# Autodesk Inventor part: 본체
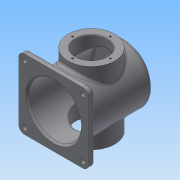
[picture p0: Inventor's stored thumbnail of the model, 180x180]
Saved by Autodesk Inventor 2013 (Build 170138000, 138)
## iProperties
Created: 2015-10
Part Number: 본체
Material: 일반
Document SubType Name: Modeling
Designer: Administrator
Density: 1 g/cm^3
Author: Administrator
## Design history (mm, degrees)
sketch "스케치1"
  geometry: C1 r 50 at (0, 0); 1 further point
  constraints: 1 centre point, 1 coincident
  dimensions: "d0" = 100 diameter of C1
extrude "돌출1" new body sketch "스케치1" stored distance "d1" = 110; taper "d2" = 0 deg
sketch "스케치2"
  geometry: C1 r 50 at (0, 0) reference; C2 r 40 at (0, 0)
  constraints: 1 centre point, 1 coincident
  dimensions: "d3" = 80 diameter of C2
extrude "돌출2" join sketch "스케치2" distance "d4" = 5; taper "d5" = 0 deg
sketch "스케치3"
  geometry: L1 (-60, 60)-(60, 60); L2 (60, 60)-(60, -60); L3 (60, -60)-(-60, -60); L4 (-60, -60)-(-60, 60); L5 (-60, 60)-(60, -60); L6 (60, 60)-(-60, -60); C1 r 50 at (0, 0) reference
  constraints: 12 end point, 2 midpoint, 2 parallel, 1 horizontal, 1 perpendicular
  dimensions: "d6" = 120 distance of L2.end L3.end; "d7" = 120 distance of L1.end L2.end
extrude "돌출3" join sketch "스케치3" distance "d8" = 10; taper "d9" = 0 deg
sketch "스케치4"
  geometry: C1 r 45 at (0, 0); 1 further point
  constraints: 1 centre point, 1 coincident
  dimensions: "d10" = 90 diameter of C1
extrude "돌출4" cut sketch "스케치4" distance "d11" = 112; taper "d12" = 0 deg
node "작업 평면1"
sketch "스케치6"
  geometry: C1 r 40 at (0, 0); 1 further point
  constraints: 1 centre point, 1 coincident
  dimensions: "d14" = 80 diameter of C1
extrude "돌출5" join sketch "스케치6" stored distance "d15" = 112; taper "d16" = 0 deg
sketch "스케치7"
  geometry: C1 r 40 at (0, 0) reference; C2 r 27 at (0, 0)
  constraints: 1 centre point, 1 coincident
  dimensions: "d17" = 54 diameter of C2
extrude "돌출6" cut sketch "스케치7" stored distance "d18" = 112; taper "d19" = 0 deg
sketch "스케치8"
  geometry: C1 r 27 at (0, 0) reference; 1 further point
  constraints: 1 vertical alignment
  dimensions: "d20" = 32.5 distance of C1.centre point (0, 32.5)
hole "구멍1" sketch "스케치8" at (0, 32.5) diameter "d21" = 3.242; stored, may be unused: countersink angle "d25" = 90 deg, drill point angle "d27" = 118 deg; dims "d22" = 8, "d23" = 4, "d24" = 2, "d26" = 10
fillet "모깎기1" dims "d31" = 5
sketch "스케치9"
  geometry: C1 r 40 at (0, 0) reference; C2 r 27 at (0, 0)
  constraints: 1 centre point, 1 coincident
  dimensions: "d32" = 54 diameter of C2
extrude "돌출7" cut sketch "스케치9" stored distance "d33" = 112; taper "d34" = 0 deg
sketch "스케치10"
  geometry: L1 (0, 0)-(22.981, 22.981); L2 (0, 0)-(32.5, 0); C1 r 40 at (0, 0) reference; 1 further point
  constraints: 4 end point, 1 coincident, 1 equal length, 1 horizontal
  dimensions: "d35" = 32.5 distance of L1.start L1.end; "d36" = 45 deg angle of L2 L1
hole "구멍2" sketch "스케치10" at (22.981, 22.981) diameter "d37" = 3.242; stored, may be unused: countersink angle "d41" = 90 deg, drill point angle "d43" = 118 deg; dims "d38" = 8, "d39" = 4, "d40" = 2, "d42" = 10
sketch "스케치11"
  geometry: L1 (-60, -60)-(60, -60) reference; C1 r 50 at (0, 0) reference; C2 r 4 at (50, -50)
  constraints: 1 centre point
  dimensions: "d47" = 8 diameter of C2; "d48" = 50 horizontal distance of C1.centre C2.centre; "d49" = 10 distance from line of L1 C2.centre
extrude "돌출8" cut sketch "스케치11" distance "d50" = 112; taper "d51" = 0 deg
fillet "모깎기2" dims "d58" = 5, "d59" = 3
chamfer "모따기1" distance "d60" = 3; stored, may be unused: second distance "d61" = 2, angle "d62" = 45 deg
fillet "모깎기3" dims "d63" = 3
fillet "모깎기4" dims "d64" = 10
fillet "모깎기5" dims "d65" = 3
chamfer "모따기2" distance "d66" = 1; stored, may be unused: second distance "d67" = 2, angle "d68" = 45 deg
node "작업 평면2"
sketch "스케치18"
  geometry: L1 (65, 50)-(65, -50) reference; 2 further points
  constraints: 1 horizontal alignment, 1 other
  dimensions: "d69" = 70 distance from line of L1 point (-5, 0)
feature "엠보싱1" sketch "스케치18" dims "d2" = 0, "d70" = 0.5, "d71" = 0
node "솔리드1"
pattern_circular "원형 패턴1" dims angle "d29" = 360 deg
mirror "대칭1"
pattern_circular "원형 패턴2" dims angle "d45" = 360 deg
pattern_linear "직사각형 패턴1" dims "d54" = 100
mirror "대칭2"
other parameters: "d13" = 62
